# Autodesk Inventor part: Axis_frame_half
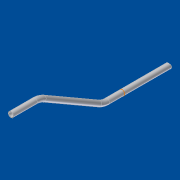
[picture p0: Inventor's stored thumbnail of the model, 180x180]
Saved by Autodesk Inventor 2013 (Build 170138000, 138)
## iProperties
Shininess: 69.0
Length Units: 11269
Angle Units: 11279
Time Units: 11290
Mass Units: 11283
Length Display Precision: 3
Angle Display Precision: 2
Created: 2001-04
Part Number: Axis_frame_half
Material: Standard
Document SubType Name: Modellieren
Designer: dl
Density: 1 g/cm^3
Density: 0.0
Volumn: 0.0
Area: 0.0
PropertySet Name: Model Information
Control State: 0
Master: False
Checked Out: False
Author: dl
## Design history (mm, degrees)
derived "Rohrprofil.ipt"
  sketch "Sketch1"
    geometry: C1 r 12.5 at (0, 0) reference; C2 r 9.5 at (0, 0) reference
sketch "Sketch4"
  geometry: L1 (-12.5, -211.352)-(12.5, -211.352) reference; L2 (0, -211.352)-(0, -204.487); A1 r 20 centre (0, -231.352) between (18.881, -224.756) and (-18.79, -224.5)
  constraints: 2 end point, 2 point on circle, 1 centre point, 1 midpoint, 1 perpendicular
  dimensions: "d14" = 20 radius of A1; "d15" = 20 distance from line of L1 A1.centre; "d16" = 0 distance from line of A1.centre L2
extrude "Extrusion1" sketch "Sketch4" dims "d17" = 50, "d18" = 0
body "Solid1"
sweep "Sweep1" dims "d7" = 0
workaxis "Work Axis1"
sketch "Sketch3"
  geometry: C1 r 9.5 at (0, 0) reference; C2 r 12.5 at (0, 0) reference
extrude "Extrusion2" join sketch "Sketch3" stored distance "d19" = 50; taper "d20" = 0 deg
sketch "Sketch2"
  geometry: L1 (0, -211.352)-(0, 69.148); L2 (10.345, 107.757)-(157.155, 362.038); L3 (167.5, 400.648)-(167.5, 509.648); A1 r 77.219 centre (90.281, 400.648) between (157.155, 362.038) and (167.5, 400.648); A2 r 77.219 centre (77.219, 69.148) between (10.345, 107.757) and (0, 69.148); 2 further points
  constraints: 6 end point, 4 point on circle, 4 point on line, 4 tangent, 2 centre point, 1 equal radius, 1 parallel, 1 vertical
  dimensions: "d3" = 150 deg angle of L1 L2; "d4" = 167.5 distance between parallel lines of L1 L3; "d5" = 721 vertical distance of L3.end L1.start; "d9" = 280.5 distance of L1.start L1.end; "d10" = 109 distance of L3.start L3.end; "d11" = 293.61851 distance of L2.start L2.end (derived)
body "Srf1"
other parameters: "d6" = 132.881 (derived)
